Omron CX-Programmer project 新工程 (CX-Programmer 4.01)

# PLC 新PLC1: CPM2* 

## Program 新程序1 (no task)

### Section 段1

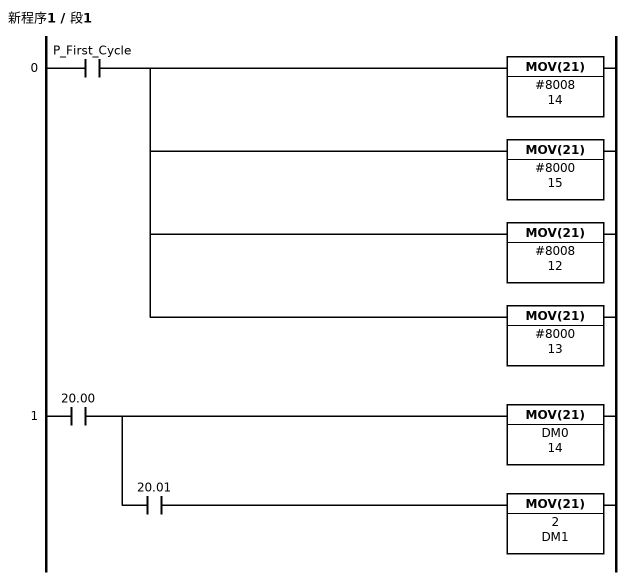
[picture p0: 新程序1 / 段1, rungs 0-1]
; rung 0
LD P_First_Cycle
MOV(21) #8008 14
MOV(21) #8000 15
MOV(21) #8008 12
MOV(21) #8000 13
; rung 1
LD 20.00
MOV(21) DM0 14
AND 20.01
MOV(21) 2 DM1

### Section END
; rung 0
END(01)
